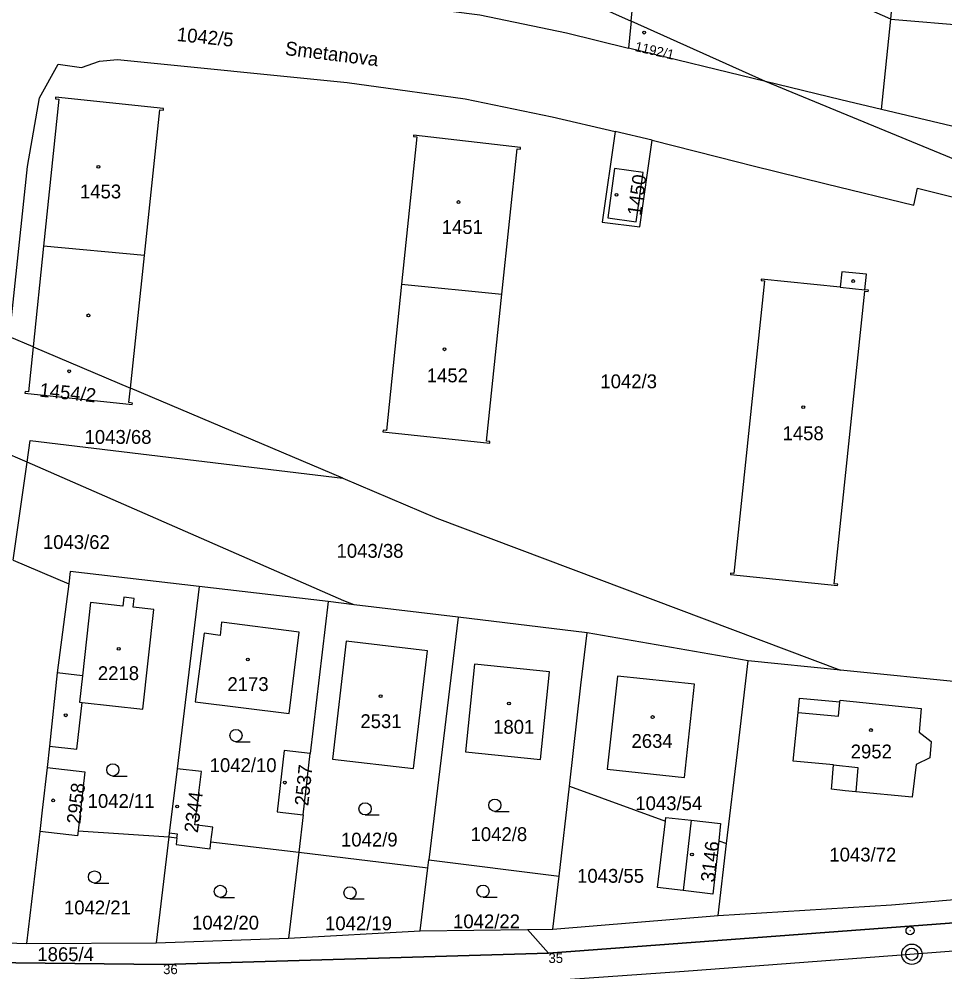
# Model space of a CAD drawing. Extents: x -779330 to -774454, y -1144748 to -1142831.
# Drawn here: x -775319.2 to -775205.5, y -1144462.2 to -1144345.1 of the extents above; entities that cross this region are included whole.
import ezdxf

# ---------------------------------------------------------------- set-up
doc = ezdxf.new("R2010")
doc.units = 0
for name, color, linetype in [('Hranice parcel', 7, 'Continuous'), ('Parcelní čísla', 7, 'Continuous'), ('Pop  PČ popisy', 7, 'Continuous'), ('SŽDC', 7, 'Continuous'), ('Vnitřní kresba', 7, 'Continuous'), ('Vrstva 1', 7, 'Continuous'), ('Vrstva 53', 7, 'Continuous'), ('Vrstva 60', 7, 'Continuous'), ('Vrstva 7', 7, 'Continuous'), ('Značky budov', 7, 'Continuous'), ('Značky kultur', 7, 'Continuous')]:
    doc.layers.add(name, color=color, linetype=linetype)

msp = doc.modelspace()

# ---------------------------------------------------------------- linework, layer by layer
at = {"layer": 'Hranice parcel'}
for p, q in [((-775212.14, -1144345.14), (-775210.05, -1144324.7)), ((-775244.01, -1144345.37), (-775242.71, -1144331.45)), ((-775261.93, -1144337.3), (-775244.01, -1144345.37)), ((-775213.28, -1144356.23), (-775212.14, -1144345.14)), ((-775244.08, -1144346.15), (-775244.32, -1144348.69)), ((-775244.01, -1144345.37), (-775244.08, -1144346.15)), ((-775227.51, -1144352.79), (-775244.01, -1144345.37)), ((-775227.51, -1144352.79), (-775244.32, -1144348.69)), ((-775182.38, -1144371.44), (-775227.51, -1144352.79)), ((-775241.44, -1144360.01), (-775245.99, -1144358.92)), ((-775272.2, -1144377.71), (-775259.89, -1144378.93)), ((-775317.45, -1144385.39), (-775320.33, -1144384.17)), ((-775317.45, -1144385.39), (-775305.49, -1144390.47)), ((-775279.4, -1144401.54), (-775305.49, -1144390.47)), ((-775318.18, -1144399.56), (-775321.4, -1144398.15)), ((-775319.89, -1144411.6), (-775313.07, -1144414.53)), ((-775313.07, -1144414.53), (-775314.51, -1144425.45)), ((-775297.04, -1144414.85), (-775299.76, -1144437.23)), ((-775281.22, -1144416.7), (-775297.04, -1144414.85)), ((-775281.22, -1144416.7), (-775283.41, -1144435.35)), ((-775278.01, -1144417.09), (-775281.22, -1144416.7)), ((-775265.25, -1144418.62), (-775278.01, -1144417.09)), ((-775265.25, -1144418.62), (-775268.87, -1144448.42)), ((-775249.4, -1144420.55), (-775265.25, -1144418.62)), ((-775229.66, -1144423.99), (-775249.4, -1144420.55)), ((-775218.3, -1144425.13), (-775229.66, -1144423.99)), ((-775314.51, -1144425.45), (-775315.45, -1144434.46)), ((-775199.5, -1144427.02), (-775218.3, -1144425.13)), ((-775315.45, -1144434.46), (-775315.74, -1144437.08)), ((-775284.3, -1144442.9), (-775283.41, -1144435.35)), ((-775252.86, -1144450.42), (-775251.58, -1144439.37)), ((-775251.58, -1144439.37), (-775239.8, -1144443.68)), ((-775284.3, -1144442.9), (-775284.84, -1144447.47)), ((-775316.63, -1144444.94), (-775318.25, -1144458.71)), ((-775311.92, -1144444.88), (-775300.78, -1144445.59)), ((-775300.78, -1144445.59), (-775302.36, -1144458.62)), ((-775295.62, -1144446.2), (-775284.84, -1144447.47)), ((-775233.32, -1144455.26), (-775232.29, -1144446.43)), ((-775233.25, -1144446.08), (-775232.29, -1144446.43)), ((-775284.84, -1144447.47), (-775286.08, -1144458.05)), ((-775284.84, -1144447.47), (-775268.99, -1144449.41)), ((-775269.93, -1144457.16), (-775268.99, -1144449.41)), ((-775268.99, -1144449.41), (-775268.87, -1144448.42)), ((-775268.87, -1144448.42), (-775252.86, -1144450.42)), ((-775253.61, -1144456.96), (-775252.86, -1144450.42)), ((-775253.61, -1144456.96), (-775233.32, -1144455.26)), ((-775286.08, -1144458.05), (-775269.93, -1144457.16)), ((-775269.93, -1144457.16), (-775256.72, -1144457)), ((-775256.72, -1144457), (-775253.61, -1144456.96)), ((-775254.16, -1144459.9), (-775256.72, -1144457)), ((-775348.99, -1144457.75), (-775318.25, -1144458.71)), ((-775318.25, -1144458.71), (-775302.36, -1144458.62)), ((-775302.36, -1144458.62), (-775286.08, -1144458.05))]:
    msp.add_line(p, q, dxfattribs=at)
for points in [[(-775212.14, -1144345.14), (-775220.88, -1144341.23), (-775242.11, -1144331.72), (-775242.71, -1144331.45)], [(-775297.97, -1144340.23), (-775277.83, -1144342.65), (-775262.59, -1144344.6), (-775251.95, -1144346.82), (-775244.32, -1144348.69)], [(-775212.14, -1144345.14), (-775202.35, -1144345.94), (-775191.45, -1144346.84), (-775185.12, -1144347.36)], [(-775320.33, -1144384.17), (-775318.15, -1144363.22), (-775316.68, -1144354.8), (-775314.36, -1144350.65), (-775311.52, -1144351.07), (-775309.28, -1144350.28), (-775307.1, -1144350.08), (-775278.88, -1144352.91), (-775272.68, -1144353.77), (-775264.39, -1144354.9), (-775253.71, -1144357.11), (-775245.99, -1144358.92)], [(-775213.28, -1144356.23), (-775218.28, -1144355.05), (-775227.51, -1144352.79)], [(-775305.49, -1144390.47), (-775303.77, -1144374.17), (-775301.87, -1144356.27), (-775301.45, -1144356.31), (-775301.43, -1144356.1), (-775314.7, -1144354.73), (-775314.72, -1144354.91), (-775314.3, -1144354.96), (-775316.17, -1144373.03), (-775317.45, -1144385.39)], [(-775189.15, -1144361.13), (-775192.34, -1144361.18), (-775213.28, -1144356.23)], [(-775259.89, -1144378.93), (-775258.02, -1144361.05), (-775257.6, -1144361.09), (-775257.58, -1144360.89), (-775270.73, -1144359.37), (-775270.75, -1144359.56), (-775270.33, -1144359.6), (-775272.2, -1144377.71)], [(-775245.99, -1144358.92), (-775247.57, -1144370.08), (-775242.95, -1144370.63), (-775241.44, -1144360.01)], [(-775241.44, -1144360.01), (-775230.77, -1144362.69), (-775229.2, -1144363.12), (-775220.08, -1144365.37), (-775209.29, -1144367.97), (-775208.86, -1144365.9), (-775203.92, -1144367.13), (-775193.75, -1144369.24), (-775184.75, -1144371.03), (-775182.38, -1144371.44)], [(-775228.03, -1144377.06), (-775228.05, -1144377.24), (-775227.63, -1144377.28), (-775231.39, -1144413.23), (-775231.8, -1144413.19), (-775231.82, -1144413.36), (-775218.67, -1144414.73), (-775218.65, -1144414.55), (-775219.07, -1144414.51), (-775215.32, -1144378.57), (-775214.9, -1144378.61), (-775214.88, -1144378.43), (-775215.31, -1144378.39), (-775215.11, -1144376.48), (-775218.15, -1144376.17), (-775218.34, -1144378.07), (-775228.03, -1144377.06)], [(-775272.2, -1144377.71), (-775274.05, -1144395.69), (-775274.47, -1144395.65), (-775274.49, -1144395.83), (-775261.38, -1144397.21), (-775261.36, -1144397.02), (-775261.78, -1144396.98), (-775259.89, -1144378.93)], [(-775317.45, -1144385.39), (-775318.02, -1144390.92), (-775318.44, -1144390.88), (-775318.46, -1144391.07), (-775305.28, -1144392.48), (-775305.26, -1144392.3), (-775305.68, -1144392.25), (-775305.49, -1144390.47)], [(-775318.18, -1144399.56), (-775317.8, -1144396.91), (-775279.4, -1144401.54)], [(-775278.01, -1144417.09), (-775279.31, -1144416.58), (-775318.18, -1144399.56)], [(-775279.4, -1144401.54), (-775267.88, -1144406.43), (-775218.3, -1144425.13)], [(-775297.04, -1144414.85), (-775312.89, -1144413), (-775313.07, -1144414.53)], [(-775315.45, -1144434.46), (-775312.07, -1144434.83), (-775311.44, -1144429.08), (-775303.96, -1144429.9), (-775302.62, -1144417.67), (-775305.15, -1144417.39), (-775305.03, -1144416.3), (-775306.33, -1144416.16), (-775306.45, -1144417.25), (-775310.4, -1144416.82), (-775311.39, -1144425.8), (-775314.51, -1144425.45)], [(-775297.53, -1144429.02), (-775286, -1144430.45), (-775284.76, -1144420.44), (-775294.33, -1144419.21), (-775294.49, -1144420.84), (-775296.46, -1144420.59), (-775297.53, -1144429.02)], [(-775251.58, -1144439.37), (-775250.19, -1144426.95), (-775249.4, -1144420.55)], [(-775269.03, -1144422.73), (-775278.99, -1144421.56), (-775280.68, -1144436.04), (-775270.72, -1144437.21), (-775269.03, -1144422.73)], [(-775264.35, -1144435.14), (-775255.13, -1144436.09), (-775254.02, -1144425.31), (-775263.24, -1144424.37), (-775264.35, -1144435.14)], [(-775232.29, -1144446.43), (-775230.97, -1144435.19), (-775229.66, -1144423.99)], [(-775236.25, -1144426.86), (-775245.7, -1144425.84), (-775246.95, -1144437.27), (-775237.48, -1144438.3), (-775236.25, -1144426.86)], [(-775216.44, -1144440.06), (-775217.73, -1144439.93), (-775219.42, -1144439.76), (-775219.38, -1144439.34), (-775219.15, -1144436.77), (-775224.12, -1144436.3), (-775223.51, -1144430.32), (-775223.34, -1144428.54), (-775218.37, -1144428.99), (-775218.35, -1144428.8), (-775208.39, -1144429.82), (-775208.66, -1144432.73), (-775207.15, -1144433.88), (-775207.33, -1144435.91), (-775209.03, -1144436.7), (-775209.5, -1144440.74), (-775216.44, -1144440.06)], [(-775283.41, -1144435.35), (-775286.61, -1144434.98), (-775287.5, -1144442.52), (-775284.3, -1144442.9)], [(-775315.74, -1144437.08), (-775316.33, -1144442.31), (-775316.59, -1144444.58), (-775316.63, -1144444.94)], [(-775315.74, -1144437.08), (-775311.1, -1144437.6), (-775311.92, -1144444.88)], [(-775299.76, -1144437.23), (-775300.73, -1144445.14), (-775300.78, -1144445.59)], [(-775295.62, -1144446.2), (-775295.4, -1144444.41), (-775297.58, -1144444.14), (-775296.78, -1144437.59), (-775299.76, -1144437.23)], [(-775233.25, -1144446.08), (-775233.97, -1144452.63), (-775237.63, -1144452.21), (-775240.77, -1144451.81), (-775239.8, -1144443.68)], [(-775239.8, -1144443.68), (-775239.75, -1144443.21), (-775236.64, -1144443.56), (-775233.02, -1144443.98), (-775233.25, -1144446.08)], [(-775311.92, -1144444.88), (-775311.98, -1144445.46), (-775316.63, -1144444.94)], [(-775300.78, -1144445.59), (-775299.79, -1144445.71), (-775299.89, -1144446.55), (-775295.72, -1144447.06), (-775295.62, -1144446.2)], [(-775088.39, -1144447.82), (-775138.01, -1144449.91), (-775170.99, -1144453.66), (-775254.16, -1144459.9)], [(-775233.32, -1144455.26), (-775212.06, -1144453.97), (-775184.99, -1144451.66)], [(-775254.16, -1144459.9), (-775301.48, -1144461.27), (-775337.71, -1144460.89), (-775341.64, -1144460.83)]]:
    msp.add_lwpolyline(points, dxfattribs=at)
at = {"layer": 'SŽDC'}
msp.add_lwpolyline([(-774890.46, -1144432.61), (-774957.77, -1144437.47), (-775003.31, -1144440.57), (-775006.9, -1144440.82), (-775032.95, -1144440.83), (-775037.63, -1144440.85), (-775036.16, -1144437.94), (-775069.78, -1144440.38), (-775071.04, -1144440.88), (-775088.39, -1144447.82), (-775138.01, -1144449.91), (-775170.99, -1144453.66), (-775254.16, -1144459.9), (-775301.48, -1144461.27), (-775337.71, -1144460.89), (-775341.64, -1144460.83), (-775351.35, -1144460.68), (-775377.95, -1144459.1), (-775417.93, -1144456.81), (-775426.17, -1144455.72)], dxfattribs=at)
at = {"layer": 'Vnitřní kresba'}
for p, q in [((-775246.06, -1144363.49), (-775246.87, -1144369.55)), ((-775242.54, -1144363.98), (-775246.06, -1144363.49)), ((-775243.39, -1144370.04), (-775242.54, -1144363.98)), ((-775246.87, -1144369.55), (-775243.39, -1144370.04)), ((-775303.77, -1144374.17), (-775316.17, -1144373.03)), ((-775218.34, -1144378.07), (-775215.31, -1144378.39)), ((-775319.89, -1144411.6), (-775318.18, -1144399.56)), ((-775311.39, -1144425.8), (-775311.75, -1144429.05)), ((-775311.75, -1144429.05), (-775311.44, -1144429.08)), ((-775218.54, -1144430.79), (-775218.37, -1144428.99)), ((-775223.51, -1144430.32), (-775218.54, -1144430.79)), ((-775219.15, -1144436.77), (-775216.16, -1144437.06)), ((-775216.16, -1144437.06), (-775216.44, -1144440.06)), ((-775236.64, -1144443.56), (-775237.63, -1144452.21)), ((-775299.73, -1144445.26), (-775300.73, -1144445.14)), ((-775299.79, -1144445.71), (-775299.73, -1144445.26))]:
    msp.add_line(p, q, dxfattribs=at)
at = {"layer": 'Vrstva 1'}
for points in [[(-774830.16, -1144431.48), (-774850.56, -1144433.02), (-774864.47, -1144434.06), (-774869.91, -1144434.47), (-774871.83, -1144434.62), (-774885.85, -1144435.68), (-774900.88, -1144436.8), (-774924.49, -1144438.59), (-774948.04, -1144440.36), (-774972.39, -1144442.2), (-774996.53, -1144444.02), (-775020.06, -1144445.79), (-775040.38, -1144447.31), (-775053.94, -1144448.33), (-775072.56, -1144449.73), (-775089.15, -1144450.96), (-775106.82, -1144452.3), (-775129.87, -1144454.04), (-775154.33, -1144455.87), (-775163.87, -1144456.59), (-775186.75, -1144458.31), (-775211.37, -1144460.17), (-775237.52, -1144462.13)], [(-775237.52, -1144462.13), (-775254.42, -1144463.35), (-775267.45, -1144464.14), (-775280.95, -1144464.78), (-775295.68, -1144465.25), (-775309.68, -1144465.5), (-775323.38, -1144465.56), (-775336.76, -1144465.43), (-775349.91, -1144465.12), (-775359.65, -1144464.79), (-775367.99, -1144464.43), (-775381.03, -1144463.72), (-775394.17, -1144462.83), (-775406.88, -1144461.77), (-775420.1, -1144460.52), (-775432.46, -1144459.19)]]:
    msp.add_lwpolyline(points, dxfattribs=at)
at = {"layer": 'Vrstva 53'}
msp.add_lwpolyline([(-775426.17, -1144455.72), (-775417.93, -1144456.81), (-775377.95, -1144459.1), (-775351.35, -1144460.68), (-775341.64, -1144460.83), (-775337.71, -1144460.89), (-775301.48, -1144461.27), (-775254.16, -1144459.9), (-775170.99, -1144453.66), (-775138.01, -1144449.91), (-775088.39, -1144447.82), (-775071.04, -1144440.88), (-775069.78, -1144440.38), (-775036.16, -1144437.94), (-775037.63, -1144440.85), (-775032.95, -1144440.83), (-775006.9, -1144440.82), (-775003.31, -1144440.57), (-774957.77, -1144437.47), (-774890.46, -1144432.61)], dxfattribs=at)
msp.add_lwpolyline([(-775426.17, -1144455.72), (-775417.93, -1144456.81), (-775377.95, -1144459.1), (-775351.35, -1144460.68), (-775341.64, -1144460.83), (-775337.71, -1144460.89), (-775301.48, -1144461.27), (-775254.16, -1144459.9), (-775170.99, -1144453.66), (-775138.01, -1144449.91), (-775088.39, -1144447.82), (-775071.04, -1144440.88), (-775069.78, -1144440.38), (-775036.16, -1144437.94), (-775037.63, -1144440.85), (-775032.95, -1144440.83), (-775006.9, -1144440.82), (-775003.31, -1144440.57), (-774957.77, -1144437.47), (-774890.46, -1144432.61)], dxfattribs=at)
at = {"layer": 'Vrstva 60'}
for p, q in [((-775254.16, -1144459.9), (-775254.16, -1144459.9)), ((-775301.48, -1144461.27), (-775301.48, -1144461.27))]:
    msp.add_line(p, q, dxfattribs=at)
at = {"layer": 'Vrstva 7'}
msp.add_line((-775209.71, -1144457.13), (-775209.81, -1144457.14), dxfattribs=at)
for centre, radius in [((-775209.76, -1144457.13), 0.5), ((-775209.54, -1144460.03), 1.25), ((-775209.54, -1144460.03), 0.752)]:
    msp.add_circle(centre, radius, dxfattribs=at)
at = {"layer": 'Značky budov'}
for centre in [(-775242.41, -1144346.78), (-775309.44, -1144363.28), (-775265.22, -1144367.6), (-775245.81, -1144366.72), (-775216.75, -1144377.31), (-775310.66, -1144381.53), (-775266.93, -1144385.69), (-775313.02, -1144388.39), (-775222.87, -1144392.8), (-775306.94, -1144422.5), (-775291.09, -1144423.8), (-775274.78, -1144428.32), (-775259.02, -1144429.21), (-775313.45, -1144430.66), (-775241.37, -1144430.88), (-775214.56, -1144432.48), (-775286.54, -1144438.94), (-775314.99, -1144441.12), (-775299.76, -1144441.88), (-775236.55, -1144447.77)]:
    msp.add_circle(centre, 0.175, dxfattribs=at)
at = {"layer": 'Značky kultur'}
for p, q in [((-775292.54, -1144433.91), (-775290.79, -1144433.91)), ((-775307.66, -1144438.13), (-775305.91, -1144438.13)), ((-775260.75, -1144442.47), (-775259, -1144442.47)), ((-775276.69, -1144442.91), (-775274.94, -1144442.91)), ((-775309.91, -1144451.28), (-775308.16, -1144451.28)), ((-775294.46, -1144453.05), (-775292.71, -1144453.05)), ((-775262.2, -1144453.02), (-775260.45, -1144453.02)), ((-775278.54, -1144453.23), (-775276.79, -1144453.23))]:
    msp.add_line(p, q, dxfattribs=at)
for centre in [(-775292.54, -1144433.16), (-775307.66, -1144437.38), (-775260.75, -1144441.72), (-775276.69, -1144442.16), (-775309.91, -1144450.53), (-775294.46, -1144452.3), (-775278.54, -1144452.48), (-775262.2, -1144452.27)]:
    msp.add_circle(centre, 0.75, dxfattribs=at)

# ---------------------------------------------------------------- texts
at = {"layer": 'Parcelní čísla'}
for s, height, rotation, p in [('1042/5', 1.7, 354, (-775299.86, -1144347.8)), ('1192/1', 1.19, 347, (-775243.63, -1144349.02)), ('1450', 1.7, 82, (-775242.82, -1144369.35)), ('1454/2', 1.7, 354, (-775316.73, -1144391.5)), ('2537', 1.7, 84, (-775283.66, -1144441.86)), ('2958', 1.7, 83, (-775311.66, -1144444.1)), ('2344', 1.7, 83, (-775297.22, -1144445.17)), ('3146', 1.7, 83, (-775233.8, -1144451.25))]:
    msp.add_text(s, height=height, rotation=rotation, dxfattribs=at).set_placement(p)
for s, p in [('1453', (-775311.7, -1144367.15)), ('1451', (-775267.27, -1144371.52)), ('1452', (-775269.11, -1144389.75)), ('1042/3', (-775247.79, -1144390.48)), ('1043/68', (-775311.13, -1144397.31)), ('1458', (-775225.42, -1144396.86)), ('1043/62', (-775316.25, -1144410.23)), ('1043/38', (-775280.19, -1144411.31)), ('2218', (-775309.5, -1144426.34)), ('2173', (-775293.59, -1144427.68)), ('2531', (-775277.26, -1144432.24)), ('1801', (-775260.96, -1144432.93)), ('2634', (-775243.97, -1144434.67)), ('2952', (-775217.05, -1144435.96)), ('1042/10', (-775295.77, -1144437.64)), ('1042/11', (-775310.75, -1144442.04)), ('1043/54', (-775243.5, -1144442.32)), ('1042/8', (-775263.73, -1144446.12)), ('1042/9', (-775279.64, -1144446.79)), ('1043/72', (-775219.67, -1144448.63)), ('1043/55', (-775250.65, -1144451.24)), ('1042/21', (-775313.66, -1144455.13)), ('1042/20', (-775297.93, -1144456.99)), ('1042/19', (-775281.6, -1144457.08)), ('1042/22', (-775265.88, -1144456.84)), ('1865/4', (-775316.93, -1144460.87))]:
    msp.add_text(s, height=1.7, dxfattribs=at).set_placement(p)
at = {"layer": 'Pop  PČ popisy'}
msp.add_text('Smetanova', height=1.7, rotation=353, dxfattribs=at).set_placement((-775286.58, -1144349.52))
at = {"layer": 'Vrstva 60'}
for s, p in [('35', (-775254.16, -1144461.1)), ('36', (-775301.48, -1144462.47))]:
    msp.add_text(s, height=1.2, dxfattribs=at).set_placement(p)

doc.saveas('drawing.dxf')
